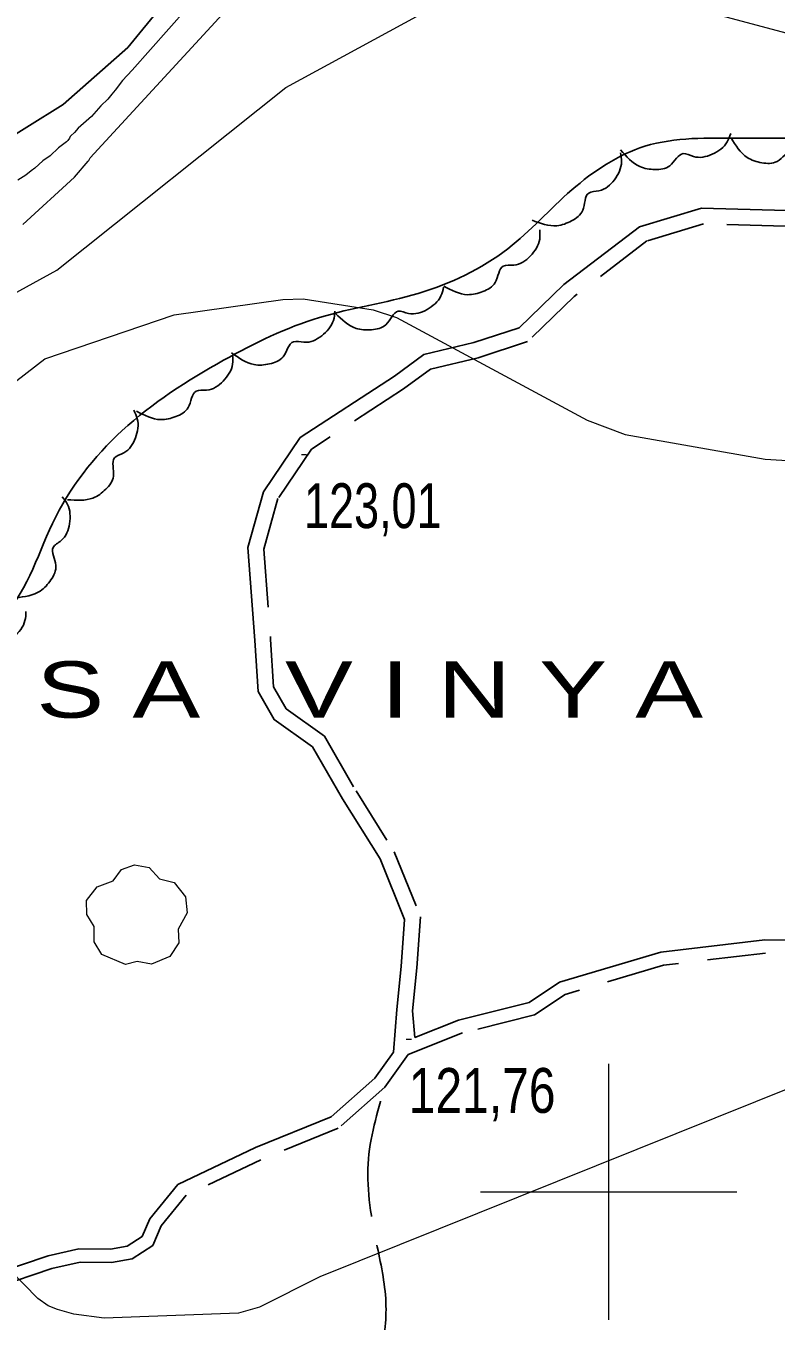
# Model space of a CAD drawing. Extents: x 483843 to 488449, y 4381269 to 4384483.
# Drawn here: x 484886.3 to 485032.7, y 4382974.8 to 4383227.6 of the extents above; entities that cross this region are included whole.
import ezdxf

# ---------------------------------------------------------------- set-up
doc = ezdxf.new("R2010")
doc.units = 0
doc.header["$LTSCALE"] = 3.8
doc.linetypes.add('LONG_DASHED', pattern=[7.5, 6, -1.5])
doc.linetypes.add('MEDIUM_DASHED', pattern=[4.5, 3, -1.5])
for name, color, linetype, lineweight in [('1', 7, 'Continuous', 13), ('27', 7, 'Continuous', 25), ('29', 7, 'Continuous', 13), ('38', 7, 'Continuous', 25), ('7', 7, 'Continuous', 13), ('8', 7, 'Continuous', 25), ('9', 7, 'Continuous', 13)]:
    doc.layers.add(name, color=color, linetype=linetype, lineweight=lineweight)
doc.layers.add('5', color=7, linetype='Continuous')

msp = doc.modelspace()

# ---------------------------------------------------------------- linework, layer by layer
at = {"layer": '1'}
for p, q in [((485000, 4383025), (485000, 4382975)), ((484975, 4383000), (485025, 4383000))]:
    msp.add_line(p, q, dxfattribs=at)
at = {"layer": '27'}
for points in [[(485368.83, 4383013.07), (485357.92, 4383017.58), (485339.7, 4383023.1), (485319.15, 4383029.84), (485302.76, 4383041.04), (485296.52, 4383049.17), (485289.67, 4383064.17), (485286.45, 4383083.98), (485285.97, 4383109.61), (485285.9, 4383115.54), (485276.33, 4383139.85), (485266.69, 4383152.65), (485256.52, 4383161.61), (485246.36, 4383180.33), (485238.82, 4383215.89), (485225.5, 4383234.69), (485215.14, 4383246.51), (485198.33, 4383264.41), (485185.34, 4383279.86), (485169.86, 4383297.33), (485163.7, 4383303.6), (485148.12, 4383317.53), (485130.86, 4383329.08), (485117.86, 4383326.04), (485107.82, 4383311.76), (485103.79, 4383302.24), (485096.18, 4383283.59), (485086.4, 4383265.77), (485083.47, 4383255.58), (485079.81, 4383240.29), (485069.46, 4383214.59), (485058.83, 4383206.45), (485039.94, 4383205.55), (485025.67, 4383205.73), (485007.1, 4383204.13), (484992.82, 4383195.6), (484980.34, 4383184.14), (484962.84, 4383175.41), (484943.61, 4383170.71), (484924.89, 4383162.35), (484905.09, 4383148.62), (484891.5, 4383130.5), (484881, 4383111.74), (484870.62, 4383107.18), (484861.85, 4383107.38), (484839.46, 4383112.83), (484820.21, 4383122.72), (484800.58, 4383135.19), (484785.62, 4383150.35), (484767.93, 4383154.78), (484745.46, 4383162.59)], [(485023.83, 4383206.61), (485023.16, 4383204.97), (485020.22, 4383202.57), (485016.56, 4383202.14), (485014.59, 4383202.72), (485011.95, 4383200.34), (485009.06, 4383199.61), (485006.09, 4383200.16), (485002.36, 4383203.44)], [(485045.61, 4383205.47), (485044.69, 4383203.96), (485041.4, 4383202.06), (485037.71, 4383202.22), (485035.87, 4383203.11), (485032.88, 4383201.18), (485029.91, 4383200.92), (485027.06, 4383201.94), (485023.91, 4383205.77)], [(485002.32, 4383202.88), (485002.53, 4383201.12), (485001.13, 4383197.59), (484998.13, 4383195.44), (484996.12, 4383194.99), (484994.97, 4383191.63), (484992.8, 4383189.59), (484989.93, 4383188.62), (484985.09, 4383189.69)], [(484986.56, 4383187.79), (484986.56, 4383186.02), (484984.73, 4383182.69), (484981.49, 4383180.92), (484979.45, 4383180.73), (484977.89, 4383177.53), (484975.48, 4383175.77), (484972.52, 4383175.16), (484967.84, 4383176.81)], [(484967.81, 4383176.61), (484967.29, 4383174.91), (484964.58, 4383172.26), (484960.97, 4383171.5), (484958.96, 4383171.91), (484956.55, 4383169.3), (484953.73, 4383168.31), (484950.72, 4383168.58), (484946.72, 4383171.51)], [(484946.59, 4383171.91), (484946.32, 4383170.15), (484944.02, 4383167.14), (484940.56, 4383165.86), (484938.51, 4383165.98), (484936.49, 4383163.04), (484933.85, 4383161.66), (484930.83, 4383161.5), (484926.45, 4383163.83)], [(484926.64, 4383163.37), (484926.63, 4383161.6), (484924.8, 4383158.28), (484921.56, 4383156.51), (484919.52, 4383156.32), (484917.96, 4383153.12), (484915.55, 4383151.36), (484912.59, 4383150.76), (484907.91, 4383152.41)], [(484907.35, 4383152.59), (484908.04, 4383150.95), (484907.67, 4383147.18), (484905.39, 4383144.27), (484903.58, 4383143.29), (484903.41, 4383139.74), (484901.89, 4383137.17), (484899.4, 4383135.46), (484894.45, 4383135.13)], [(484893.41, 4383135.68), (484894.42, 4383134.23), (484894.82, 4383130.45), (484893.18, 4383127.15), (484891.61, 4383125.82), (484892.16, 4383122.31), (484891.19, 4383119.49), (484889.1, 4383117.3), (484884.32, 4383115.98)], [(484886.31, 4383113.28), (484886.13, 4383111.52), (484883.98, 4383108.39), (484880.58, 4383106.95), (484878.53, 4383106.97), (484876.66, 4383103.94), (484874.09, 4383102.42), (484871.08, 4383102.12), (484866.59, 4383104.23)]]:
    msp.add_spline(points, degree=3, dxfattribs=at)
at = {"layer": '29'}
msp.add_lwpolyline([(484905.76, 4383044.37), (484901.15, 4383046.34), (484899.65, 4383048.82), (484899.64, 4383051.81), (484898.19, 4383054.17), (484898.13, 4383056.92), (484900.2, 4383059.59), (484903.36, 4383060.7), (484904.93, 4383062.95), (484907.47, 4383063.87), (484910.35, 4383063.32), (484912.38, 4383061.12), (484915.21, 4383060.39), (484917.44, 4383057.62), (484917.79, 4383054.5), (484916.02, 4383051.29), (484916.12, 4383048.61), (484914.39, 4383045.94), (484910.82, 4383044.47), (484908.03, 4383045)], close=True, dxfattribs=at)
at = {"layer": '38'}
for points in [[(485034.7, 4383191.59), (485018.14, 4383192.03), (485006.06, 4383188.41), (484991.29, 4383177.15), (484982.54, 4383168.69), (484973.7, 4383165.81), (484963.94, 4383163.48), (484958.22, 4383159.27), (484939.84, 4383147.25), (484932.68, 4383136.68), (484929.63, 4383125.82), (484931, 4383107.66), (484931.6, 4383097.7), (484934.77, 4383092.22), (484942.23, 4383086.87), (484948.09, 4383076.74), (484955.41, 4383065.01), (484960.21, 4383053.21), (484959.53, 4383044.02), (484958.66, 4383035.58), (484958.05, 4383027.29)], [(485228.14, 4382973.2), (485209.05, 4382995.85), (485184.68, 4383015.99), (485169.44, 4383026.46), (485151.64, 4383038.49), (485126.3, 4383049.12), (485106.57, 4383057.5), (485098.92, 4383059.22), (485091.57, 4383058.52), (485078.22, 4383055.02), (485074.86, 4383051.83), (485059.81, 4383048.91), (485047.48, 4383049.02), (485030.47, 4383049.23), (485010.21, 4383046.82), (484990.45, 4383040.92), (484984.51, 4383036.97), (484970.73, 4383033.51), (484962.19, 4383030.13)], [(484958.05, 4383027.29), (484954.41, 4383022.21), (484945.89, 4383014.68), (484931.12, 4383008.66), (484915.96, 4383001.44), (484910.46, 4382994.74), (484908.99, 4382991.27), (484906.09, 4382989.4), (484902.81, 4382988.8), (484896.62, 4382988.86), (484890.66, 4382987.52), (484874.79, 4382982.16), (484862.61, 4382981.24), (484853.53, 4382982), (484843.02, 4382983.85), (484832.72, 4382982.71), (484822.89, 4382979.63), (484812.79, 4382978.98), (484803.44, 4382978.42), (484790.92, 4382973.86), (484780.05, 4382970.81), (484772.26, 4382970.81), (484763.01, 4382967.18), (484754.56, 4382963.25)]]:
    msp.add_lwpolyline(points, dxfattribs=at)
at = {"layer": '38', "linetype": 'MEDIUM_DASHED'}
for points in [[(485034.46, 4383188.53), (485018.55, 4383188.96), (485007.47, 4383185.64), (484993.29, 4383174.82), (484984.16, 4383165.99), (484974.53, 4383162.85), (484965.25, 4383160.64), (484959.96, 4383156.75), (484942.03, 4383145.02), (484935.49, 4383135.38), (484932.73, 4383125.51), (484934.06, 4383107.86), (484934.61, 4383098.61), (484937.1, 4383094.32), (484944.56, 4383088.97), (484950.72, 4383078.31), (484958.15, 4383066.41), (484963.32, 4383053.7), (484962.59, 4383043.75), (484961.72, 4383035.32), (484962.19, 4383030.13)], [(485047.46, 4383046.44), (485030.61, 4383046.64), (485010.74, 4383044.27), (484991.56, 4383038.55), (484985.57, 4383034.57), (484971.52, 4383031.04), (484960.91, 4383026.85), (484956.34, 4383020.46), (484947.27, 4383012.45), (484932.16, 4383006.29), (484917.59, 4382999.35), (484912.7, 4382993.39), (484911.06, 4382989.52), (484907.06, 4382986.95), (484903.04, 4382986.21), (484896.89, 4382986.27), (484891.36, 4382985.03), (484875.3, 4382979.6)]]:
    msp.add_lwpolyline(points, dxfattribs=at)
at = {"layer": '38', "linetype": 'LONG_DASHED'}
msp.add_spline([(484955.47, 4382967.03), (484956.57, 4382977.74), (484954.87, 4382989.29), (484953.08, 4383005.5), (484956.34, 4383020.46)], degree=3, dxfattribs=at)
at = {"layer": '7'}
for p, q in [((484940.08, 4383143.96), (484941.08, 4383143.96)), ((484960.52, 4383029.8), (484961.52, 4383029.8))]:
    msp.add_line(p, q, dxfattribs=at)
at = {"layer": '8'}
msp.add_lwpolyline([(484639.18, 4383240.24), (484659.63, 4383223.28), (484699.6, 4383184.22), (484702.32, 4383182.15), (484718.73, 4383173.5), (484720.49, 4383172.79), (484721.94, 4383172.56), (484723.08, 4383172.49), (484801.98, 4383180.91), (484870.11, 4383199.58), (484879.36, 4383203.46), (484893.59, 4383212.28), (484906.22, 4383223.44), (484919.7, 4383240.01)], dxfattribs=at)
at = {"layer": '9'}
for points in [[(484885.68, 4383188.86), (484895.77, 4383198.07), (484898.48, 4383201.2), (484898.59, 4383201.36), (484898.87, 4383201.87), (484955.97, 4383263.95)], [(484991.92, 4383237.73), (485037.51, 4383225.48)], [(484921.32, 4383235.19), (484907.07, 4383219.02), (484905.14, 4383216.95), (484903.74, 4383215.08), (484903.05, 4383214.33), (484902.27, 4383213.3), (484900.96, 4383212.04), (484899.12, 4383209.95), (484896.5, 4383207.64), (484895.8, 4383206.84), (484895.08, 4383206.2), (484894.96, 4383206.04), (484894.8, 4383205.7), (484894.52, 4383205.27), (484894.23, 4383205), (484892.67, 4383203.84), (484891.03, 4383202.25), (484889.62, 4383201.27), (484888.04, 4383199.84), (484887.33, 4383199.36), (484886.31, 4383198.5)], [(484875.83, 4383170.89), (484892.34, 4383179.95), (484937.04, 4383215.61), (484968.5, 4383232.8)], [(484886.31, 4383198.5), (484884.74, 4383197.5)], [(484861.44, 4383140.55), (484890.03, 4383162.65), (484915.27, 4383171.25), (484936.42, 4383174.25), (484940.43, 4383174.37), (484954.06, 4383172.22), (484958.6, 4383170.73), (484995.84, 4383150.68), (485003.26, 4383147.86), (485030.56, 4383143.08), (485040.22, 4383142.47)], [(485036.29, 4383020.67), (484943.64, 4382983.39), (484931.91, 4382977.51), (484927.82, 4382976.34), (484901.55, 4382975.38), (484895.63, 4382976.14), (484892.46, 4382977.04), (484890.67, 4382977.79), (484888.66, 4382979.2), (484880.46, 4382987.55)]]:
    msp.add_lwpolyline(points, dxfattribs=at)

# ---------------------------------------------------------------- texts
at = {"layer": '5', "width": 1.35}
msp.add_text('S A   V I N Y A', height=10.99, dxfattribs=at).set_placement((484888.35, 4383092.58))
at = {"layer": '7'}
for s, width, p in [('123,01', 0.75, (484940.58, 4383129.59)), ('121,76', 0.8, (484961.02, 4383015.43))]:
    msp.add_text(s, height=8.75, dxfattribs=dict(at, width=width)).set_placement(p)

doc.saveas('drawing.dxf')
